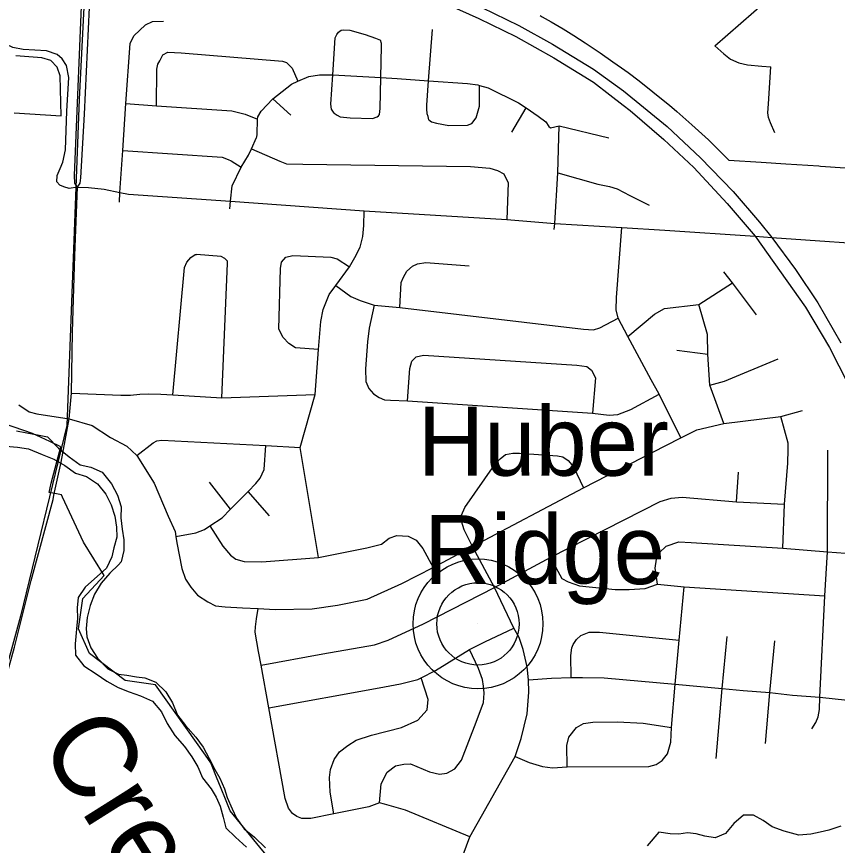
# Model space of a CAD drawing. Extents: x 0 to 34, y 0 to 22.
# Drawn here: x 5.063 to 6.003, y 18.158 to 19.107 of the extents above; entities that cross this region are included whole.
import ezdxf

# ---------------------------------------------------------------- set-up
doc = ezdxf.new("R2010")
doc.units = 0
for name, color, linetype in [('GM_X_City_Street', 7, 'Continuous'), ('GM_X_Corporation', 7, 'Continuous'), ('GM_X_County_Road', 7, 'Continuous'), ('GM_X_Interstate_Route', 7, 'Continuous'), ('GM_X_Major_River', 7, 'Continuous'), ('GM_X_Major_River_Text', 7, 'Continuous'), ('GM_X_Minor_River', 7, 'Continuous'), ('GM_X_Rail_Line', 7, 'Continuous'), ('GM_X_State_Route', 7, 'Continuous'), ('GM_X_Township_Road', 7, 'Continuous'), ('GM_X_Unincorporated', 7, 'Continuous'), ('GM_X_Unincorporated_Location', 7, 'Continuous'), ('GM_X_Unincorporated_Text', 7, 'Continuous')]:
    doc.layers.add(name, color=color, linetype=linetype)

msp = doc.modelspace()

# ---------------------------------------------------------------- linework, layer by layer
at = {"layer": 'GM_X_City_Street'}
for points in [[(5.86241, 19.07357), (5.92215, 19.1255), (5.93857, 19.14031), (5.9445, 19.14416)], [(5.86241, 19.07357), (5.87288, 19.06433), (5.88048, 19.05858), (5.89013, 19.05427), (5.90019, 19.05181), (5.9164, 19.05058), (5.92666, 19.04975)], [(5.93138, 18.97397), (5.92641, 18.98542), (5.92425, 18.99169), (5.92339, 18.99688), (5.92403, 19.00725), (5.92666, 19.04975)]]:
    msp.add_lwpolyline(points, dxfattribs=at)
at = {"layer": 'GM_X_Corporation'}
for points in [[(5.66238, 19.10853), (5.66496, 19.10707), (5.675, 19.10124), (5.68904, 19.09297), (5.70089, 19.0856), (5.7141, 19.07727), (5.73128, 19.06555), (5.74593, 19.0554), (5.75567, 19.04857), (5.76344, 19.04304), (5.765, 19.04185), (5.77435, 19.03465), (5.78348, 19.02753), (5.79972, 19.01466), (5.81061, 19.00587), (5.81902, 18.99853), (5.83621, 18.98326), (5.85542, 18.96589), (5.8787, 18.94287), (5.91583, 18.94045), (5.94405, 18.93858), (5.98175, 18.93608), (5.98364, 18.93595), (6.01191, 18.93408)], [(5.05997, 18.99684), (5.11381, 18.99352), (5.11254, 19.03933), (5.10943, 19.04941), (5.10194, 19.05684), (5.09183, 19.05987), (5.06178, 19.06204)], [(5.3588, 18.13419), (5.33787, 18.15995), (5.30744, 18.19739), (5.3021, 18.21064), (5.29722, 18.22273), (5.29195, 18.2358), (5.2869, 18.24832), (5.28533, 18.2522), (5.27901, 18.26111), (5.22175, 18.34177), (5.18707, 18.34673), (5.14638, 18.37743), (5.13374, 18.40563), (5.13852, 18.44052), (5.16319, 18.46676), (5.13946, 18.50497), (5.11532, 18.55673), (5.11423, 18.55914), (5.11035, 18.55993), (5.09996, 18.56198), (5.10245, 18.57253), (5.11328, 18.61425), (5.1007, 18.62055), (5.08109, 18.62959), (5.03738, 18.64436)]]:
    msp.add_lwpolyline(points, dxfattribs=at)
at = {"layer": 'GM_X_County_Road'}
for points in [[(5.1325, 18.91193), (5.14519, 18.91151), (5.16323, 18.90941), (5.18122, 18.90564), (5.19082, 18.90371), (5.3079, 18.89575), (5.46101, 18.88479), (5.62446, 18.87486), (5.67932, 18.87032), (5.75588, 18.86555), (5.80515, 18.86234)], [(5.80515, 18.86234), (5.90861, 18.8556), (5.92792, 18.85423), (6.07124, 18.84411), (6.08009, 18.84353)]]:
    msp.add_lwpolyline(points, dxfattribs=at)
at = {"layer": 'GM_X_Interstate_Route'}
msp.add_line((5.74217, 19.01763), (5.75777, 19.00562), dxfattribs=at)
for points in [[(4.24891, 19.48616), (4.36443, 19.45657), (4.47706, 19.42735), (4.80123, 19.34181), (4.93621, 19.30635), (5.14378, 19.25182), (5.15288, 19.24943), (5.37233, 19.1927), (5.45831, 19.16923), (5.51314, 19.15256), (5.55876, 19.13413), (5.59561, 19.11769), (5.63794, 19.09707), (5.67679, 19.07577), (5.7235, 19.04681), (5.7579, 19.02224), (5.80795, 18.98123), (5.84611, 18.94527), (5.88361, 18.90666), (5.91388, 18.87157), (5.92792, 18.85423), (5.95512, 18.8174), (5.98056, 18.77923), (6.00688, 18.73361)], [(5.37096, 19.17937), (5.455, 19.15643), (5.509, 19.13981), (5.55545, 19.12134), (5.5923, 19.10489), (5.63463, 19.08427), (5.67806, 19.05993), (5.72346, 19.03204), (5.74217, 19.01763)], [(5.75777, 19.00562), (5.76557, 18.99961), (5.80417, 18.96649), (5.83861, 18.93425), (5.87677, 18.89302), (5.90861, 18.8556), (5.96626, 18.77436), (5.99389, 18.72808), (6.02585, 18.665), (6.03622, 18.64167), (6.04872, 18.61184), (6.05838, 18.58464), (6.07022, 18.54757), (6.07965, 18.51314), (6.08733, 18.4809), (6.09171, 18.4605), (6.09632, 18.43352), (6.10005, 18.40282), (6.104, 18.3754), (6.10575, 18.34755)]]:
    msp.add_lwpolyline(points, dxfattribs=at)
at = {"layer": 'GM_X_Major_River'}
for points in [[(5.06261, 18.63267), (5.07436, 18.63034), (5.08686, 18.628), (5.09823, 18.62567), (5.11068, 18.6127), (5.12315, 18.60277), (5.13562, 18.5936), (5.14775, 18.59089), (5.16061, 18.58513), (5.17155, 18.57179), (5.17831, 18.55885), (5.18242, 18.54555), (5.18236, 18.53302), (5.18381, 18.5201), (5.18565, 18.50757), (5.18558, 18.49542), (5.18249, 18.48252)], [(5.03787, 18.61381), (5.05039, 18.61489), (5.06366, 18.61406), (5.07654, 18.61211), (5.09206, 18.60558), (5.10531, 18.6002), (5.11817, 18.59292), (5.13026, 18.58414), (5.14276, 18.58028), (5.15562, 18.57187), (5.16504, 18.56005), (5.17105, 18.54788), (5.17516, 18.53495), (5.17737, 18.52241), (5.17769, 18.51064), (5.17422, 18.49851), (5.1719, 18.48827), (5.16576, 18.47539), (5.14138, 18.45348), (5.13336, 18.44175), (5.13216, 18.42999), (5.13248, 18.41746), (5.13143, 18.40594)], [(5.18249, 18.48252), (5.17965, 18.47919), (5.16953, 18.46968), (5.15961, 18.45795), (5.15196, 18.44546), (5.14697, 18.43258), (5.14349, 18.41892), (5.14229, 18.40602), (5.14338, 18.39652), (5.14787, 18.38398), (5.1554, 18.37217), (5.16747, 18.35997), (5.17958, 18.35384), (5.18906, 18.35265), (5.20005, 18.3507)], [(5.13143, 18.40594), (5.13092, 18.4012), (5.12969, 18.38862), (5.13038, 18.37571), (5.1398, 18.36351), (5.15379, 18.35434), (5.16627, 18.34592), (5.17913, 18.33865), (5.19162, 18.33366), (5.20487, 18.32904), (5.2185, 18.3229), (5.22868, 18.3107), (5.23544, 18.29738), (5.2441, 18.28367), (5.25503, 18.27109), (5.26332, 18.25929), (5.27047, 18.24786), (5.27572, 18.23493), (5.28552, 18.22236), (5.29154, 18.21284), (5.29604, 18.20256), (5.29939, 18.19002), (5.30237, 18.17786), (5.31369, 18.16717), (5.32615, 18.15572)], [(5.20005, 18.3507), (5.20952, 18.34952), (5.2224, 18.34452), (5.23372, 18.33346), (5.24124, 18.32089), (5.24724, 18.30682), (5.25629, 18.29501), (5.26798, 18.28166), (5.27665, 18.27023), (5.28341, 18.25729), (5.2898, 18.24473), (5.29544, 18.23484), (5.30107, 18.22266), (5.30405, 18.2124), (5.30968, 18.19946), (5.31456, 18.18881), (5.3236, 18.17662), (5.33531, 18.16707), (5.34777, 18.15486)]]:
    msp.add_lwpolyline(points, dxfattribs=at)
at = {"layer": 'GM_X_Minor_River'}
msp.add_lwpolyline([(6.00677, 18.17981), (5.99306, 18.17502), (5.98317, 18.17284), (5.97253, 18.17066), (5.95885, 18.16928), (5.9422, 18.174), (5.92821, 18.17908), (5.91803, 18.18639), (5.9067, 18.19219), (5.89532, 18.19231), (5.88422, 18.18293), (5.875, 18.17125), (5.86281, 18.16644), (5.85106, 18.16845), (5.84122, 18.17083), (5.83136, 18.17207), (5.82148, 18.17064), (5.81124, 18.17112), (5.79835, 18.17277), (5.78492, 18.15734)], dxfattribs=at)
at = {"layer": 'GM_X_Rail_Line'}
msp.add_lwpolyline([(5.013, 20.2642), (5.1449, 19.80142), (5.15727, 19.72918), (5.15969, 19.50896), (5.13444, 19.0127), (5.12013, 18.63864), (5.06738, 18.42023), (5.01943, 18.24707), (4.96758, 18.0163), (4.96155, 17.92727), (4.95651, 17.64256), (4.86303, 17.64736)], dxfattribs=at)
at = {"layer": 'GM_X_State_Route'}
for points in [[(5.1325, 18.91193), (5.12962, 18.91646), (5.12904, 18.92531), (5.13696, 19.11901), (5.13922, 19.15801), (5.13991, 19.17464), (5.14038, 19.18575), (5.14273, 19.2287), (5.14318, 19.23857), (5.14378, 19.25182), (5.1465, 19.30769), (5.14778, 19.34656), (5.14838, 19.35872)], [(5.1325, 18.91193), (5.13544, 18.9162), (5.13638, 18.92253), (5.14047, 18.9954), (5.14611, 19.11753), (5.14843, 19.15766), (5.14913, 19.17429), (5.14959, 19.1854), (5.15162, 19.22642)], [(5.10555, 18.55897), (5.11371, 18.59669), (5.12314, 18.64647), (5.12556, 18.67565), (5.12665, 18.74583), (5.12954, 18.83359), (5.1325, 18.91193)], [(5.0472, 18.33612), (5.06027, 18.38488), (5.0795, 18.46117), (5.1045, 18.55414), (5.10555, 18.55897)]]:
    msp.add_lwpolyline(points, dxfattribs=at)
at = {"layer": 'GM_X_Township_Road'}
for p, q in [((5.53458, 19.03363), (5.53906, 19.09222)), ((5.35621, 19.01294), (5.37675, 18.99444)), ((5.62997, 18.97472), (5.6463, 19.00249)), ((5.68423, 18.98208), (5.74123, 18.96831)), ((5.8192, 18.72521), (5.85449, 18.72052)), ((5.88755, 18.55137), (5.88977, 18.58527)), ((5.30796, 18.54297), (5.28382, 18.57387)), ((5.3525, 18.53533), (5.32789, 18.56317))]:
    msp.add_line(p, q, dxfattribs=at)
for points in [[(5.1325, 18.91193), (5.12293, 18.91011), (5.11676, 18.91231), (5.11234, 18.91408), (5.10882, 18.91783), (5.10926, 18.92511), (5.11279, 18.93327), (5.11587, 18.94054), (5.11896, 18.95444), (5.12028, 18.99899), (5.12249, 19.03736), (5.11984, 19.05104), (5.11499, 19.05898), (5.10926, 19.06382), (5.09692, 19.06779), (5.07046, 19.06956), (5.05855, 19.07176), (5.05062, 19.07573), (5.03739, 19.08368), (5.02008, 19.09142), (5.01777, 19.09728)], [(5.18048, 18.89454), (5.18122, 18.90564), (5.18445, 18.95364), (5.18807, 19.00754), (5.19269, 19.07632), (5.19697, 19.08501), (5.21043, 19.09774), (5.21846, 19.10143), (5.23101, 19.10203)], [(5.42655, 18.99644), (5.42357, 19.00103), (5.42288, 19.00674), (5.42519, 19.04053), (5.42761, 19.08269), (5.42956, 19.08684), (5.43149, 19.08947), (5.43456, 19.09171)], [(5.43456, 19.09171), (5.43687, 19.09215), (5.44444, 19.09158), (5.46224, 19.08678), (5.47396, 19.08245), (5.47964, 19.08009)], [(5.47744, 18.99348), (5.4786, 18.99498), (5.47906, 19.00182), (5.4799, 19.03727), (5.48075, 19.07338), (5.48073, 19.07628), (5.47964, 19.08009)], [(5.22297, 19.00512), (5.22349, 19.04703), (5.2247, 19.05271), (5.22703, 19.05648), (5.23015, 19.06328)], [(5.23015, 19.06328), (5.23589, 19.06624), (5.25146, 19.06566), (5.36724, 19.05613), (5.37178, 19.05455), (5.37855, 19.048), (5.38508, 19.03305)], [(5.33816, 18.97211), (5.33882, 18.98955), (5.3391, 18.99228), (5.34298, 18.99869), (5.35621, 19.01294), (5.37756, 19.02977), (5.38508, 19.03305), (5.3975, 19.03838), (5.40961, 19.04036), (5.42101, 19.04059), (5.42519, 19.04053)], [(5.42519, 19.04053), (5.4799, 19.03727), (5.49886, 19.03613), (5.53458, 19.03363), (5.57935, 19.0305), (5.59111, 19.02883), (5.59307, 19.02829), (5.60285, 19.02563), (5.6376, 19.00845), (5.6463, 19.00249), (5.66021, 18.99295), (5.66888, 18.98675), (5.67261, 18.98138), (5.67449, 18.97983), (5.68423, 18.98208)], [(5.53514, 18.98891), (5.53405, 18.99273), (5.53294, 18.99578), (5.53263, 19.00148), (5.53268, 19.00566), (5.53458, 19.03363)], [(5.58411, 18.98483), (5.58913, 18.99123), (5.59309, 19.00448), (5.59307, 19.02829)], [(5.18807, 19.00754), (5.22297, 19.00512), (5.30916, 18.99914), (5.3247, 18.99552), (5.33882, 18.98955)], [(5.42655, 18.99644), (5.42995, 18.99411), (5.43334, 18.99217), (5.44473, 18.99125), (5.47056, 18.99053), (5.4759, 18.99236), (5.47744, 18.99348)], [(5.53514, 18.98891), (5.53815, 18.98659), (5.54384, 18.985), (5.55787, 18.98253), (5.57914, 18.98262), (5.58411, 18.98483)], [(5.67836, 18.86324), (5.67932, 18.87032), (5.68269, 18.92815), (5.68423, 18.98208)], [(5.30701, 18.88676), (5.3079, 18.89575), (5.30964, 18.91325), (5.32002, 18.93486), (5.3283, 18.94835), (5.33197, 18.9558), (5.33764, 18.96855), (5.33806, 18.9695), (5.33816, 18.97211)], [(5.18445, 18.95364), (5.29826, 18.94609), (5.30506, 18.94333), (5.30846, 18.94177), (5.32002, 18.93486)], [(5.33197, 18.9558), (5.36432, 18.94141), (5.37188, 18.93864), (5.39049, 18.93801), (5.58253, 18.93546), (5.60487, 18.93353), (5.61373, 18.93084), (5.62105, 18.92699), (5.62568, 18.91659), (5.62446, 18.87486)], [(5.68269, 18.92815), (5.72842, 18.91528), (5.74207, 18.91244), (5.75078, 18.91004), (5.76512, 18.90225), (5.78741, 18.89131)], [(5.40854, 18.48746), (5.38769, 18.61351), (5.40475, 18.67419), (5.40861, 18.72596), (5.41118, 18.75779), (5.41407, 18.77162), (5.42082, 18.78866), (5.42854, 18.79895), (5.44429, 18.82048), (5.45008, 18.8311), (5.45651, 18.84299), (5.4594, 18.85521), (5.46037, 18.86775), (5.46101, 18.88479)], [(5.78977, 18.69096), (5.76281, 18.74055), (5.75183, 18.76154), (5.74971, 18.77117), (5.74991, 18.78523), (5.75588, 18.86555)], [(5.24168, 18.67392), (5.25529, 18.81974), (5.25765, 18.82579), (5.26227, 18.83105), (5.26725, 18.83478), (5.26877, 18.83476)], [(5.29792, 18.67024), (5.30437, 18.8244), (5.3044, 18.82706), (5.3014, 18.83014), (5.29725, 18.83248), (5.26877, 18.83476)], [(5.40861, 18.72596), (5.38224, 18.72789), (5.37453, 18.73271), (5.36809, 18.73946), (5.36327, 18.74911), (5.3652, 18.81856), (5.36617, 18.82595), (5.37131, 18.83142), (5.37903, 18.83367), (5.42276, 18.83142), (5.42983, 18.82949), (5.44429, 18.82048)], [(5.50184, 18.77387), (5.50345, 18.80248), (5.50603, 18.80859), (5.50988, 18.81566), (5.51632, 18.82113), (5.5221, 18.82402), (5.53143, 18.82531), (5.58126, 18.82177)], [(5.91034, 18.76558), (5.883, 18.80218), (5.87298, 18.81489)], [(5.76281, 18.74055), (5.79363, 18.76635), (5.8048, 18.7729), (5.84409, 18.77753), (5.883, 18.80218)], [(5.42854, 18.79895), (5.44558, 18.78641), (5.45651, 18.7819), (5.47227, 18.77676), (5.50184, 18.77387), (5.71233, 18.74904), (5.72372, 18.74852), (5.73097, 18.7507), (5.75183, 18.76154)], [(5.47227, 18.77676), (5.4668, 18.7504), (5.46455, 18.73464), (5.4623, 18.70378), (5.46294, 18.68899), (5.46616, 18.68127), (5.47162, 18.67516), (5.47805, 18.67066), (5.48416, 18.66808), (5.49091, 18.66777), (5.51052, 18.66712), (5.72249, 18.65269), (5.74165, 18.65049), (5.7516, 18.65122), (5.76634, 18.65712), (5.79876, 18.67444)], [(5.87281, 18.64091), (5.85697, 18.68512), (5.85449, 18.72052), (5.8541, 18.74286), (5.84409, 18.77753)], [(5.51052, 18.66712), (5.5131, 18.7041), (5.51567, 18.71246), (5.52058, 18.71754), (5.52869, 18.71939), (5.70444, 18.70796), (5.71586, 18.70649), (5.72139, 18.70207), (5.72581, 18.69323), (5.72249, 18.65269)], [(5.85697, 18.68512), (5.87355, 18.68954), (5.93508, 18.71496)], [(5.82381, 18.62469), (5.79876, 18.67444), (5.78977, 18.69096)], [(5.12556, 18.67565), (5.18236, 18.67367), (5.19333, 18.67367), (5.20386, 18.67477), (5.214, 18.67513), (5.22784, 18.67452)], [(5.22784, 18.67452), (5.24168, 18.67392), (5.29792, 18.67024), (5.40475, 18.67419)], [(5.06524, 18.66249), (5.07709, 18.65437), (5.08586, 18.65196), (5.12314, 18.64647)], [(5.80664, 18.61585), (5.82381, 18.62469), (5.84186, 18.6339), (5.87281, 18.64091), (5.93803, 18.64901), (5.96314, 18.65603)], [(5.94064, 18.49812), (5.94245, 18.54843), (5.94614, 18.59559), (5.9465, 18.61143), (5.9465, 18.61843), (5.93803, 18.64901)], [(5.12314, 18.64647), (5.14946, 18.63858), (5.17045, 18.62517), (5.18895, 18.61504), (5.20068, 18.60446), (5.22034, 18.57282), (5.23622, 18.53498), (5.24437, 18.51739), (5.24534, 18.51144), (5.24649, 18.50445), (5.2522, 18.47473), (5.25623, 18.46251), (5.26221, 18.45369), (5.27007, 18.44447), (5.28175, 18.43671), (5.29044, 18.43203), (5.30183, 18.43113), (5.32157, 18.42972), (5.33944, 18.42893), (5.35879, 18.42808), (5.40136, 18.42865), (5.43029, 18.43283), (5.4642, 18.43959), (5.50418, 18.45782), (5.53991, 18.4761), (5.58519, 18.5002), (5.71218, 18.56722), (5.80664, 18.61585)], [(5.20068, 18.60446), (5.21939, 18.61881), (5.22359, 18.62103), (5.22931, 18.6221), (5.34823, 18.61565), (5.38769, 18.61351)], [(5.24534, 18.51144), (5.26791, 18.51594), (5.27783, 18.51961), (5.28415, 18.52378), (5.29814, 18.53302), (5.30796, 18.54297), (5.32789, 18.56317), (5.337, 18.5724), (5.34164, 18.57842), (5.34631, 18.58824), (5.34823, 18.61565)], [(5.58519, 18.5002), (5.57564, 18.51931), (5.57232, 18.52928), (5.57235, 18.53609), (5.57622, 18.54493), (5.61048, 18.59393), (5.61675, 18.60056), (5.62283, 18.60535), (5.63131, 18.6072), (5.63886, 18.6072), (5.68251, 18.60388), (5.68841, 18.60277), (5.69467, 18.59872), (5.70057, 18.59154), (5.71218, 18.56722)], [(5.97387, 18.29107), (5.97844, 18.29849), (5.98114, 18.30493), (5.98239, 18.31344), (5.9828, 18.32736), (5.98841, 18.4437), (5.99174, 18.49396), (5.99222, 18.61043)], [(5.34277, 18.36422), (5.41365, 18.37718), (5.47268, 18.38742), (5.48832, 18.39291), (5.52869, 18.4117), (5.61012, 18.45325), (5.67473, 18.48773), (5.79987, 18.55175), (5.81239, 18.55543), (5.82529, 18.55654), (5.88755, 18.55137), (5.94245, 18.54843)], [(5.28415, 18.52378), (5.29887, 18.50033), (5.30788, 18.49032), (5.3139, 18.48568), (5.32336, 18.4829), (5.3435, 18.48263), (5.40854, 18.48746), (5.46378, 18.49851), (5.48093, 18.50284), (5.48964, 18.50975), (5.49836, 18.51266), (5.51125, 18.51183), (5.52039, 18.50726), (5.52828, 18.49771), (5.53991, 18.4761)], [(5.60771, 17.95043), (5.6051, 17.95859), (5.59941, 17.97641), (5.5742, 18.05748), (5.57087, 18.07413), (5.56969, 18.08979), (5.57047, 18.11213), (5.57224, 18.13543), (5.57439, 18.14699), (5.58203, 18.16737), (5.63402, 18.25964), (5.64087, 18.28), (5.64752, 18.30845), (5.64939, 18.33318), (5.64897, 18.3473), (5.64773, 18.36226), (5.64295, 18.38221), (5.63859, 18.39571), (5.63236, 18.40672), (5.61012, 18.45325), (5.58519, 18.5002)], [(5.79688, 18.45699), (5.79439, 18.47527), (5.79563, 18.48566), (5.79896, 18.49272), (5.80685, 18.50061), (5.8214, 18.5056), (5.83552, 18.50477), (5.94064, 18.49812), (5.99174, 18.49396), (6.03287, 18.49106)], [(5.67473, 18.48773), (5.68055, 18.4761), (5.6872, 18.46364), (5.69467, 18.45948), (5.70755, 18.45491), (5.74827, 18.45075), (5.76447, 18.45075), (5.78275, 18.452), (5.79688, 18.45699), (5.82763, 18.45408), (5.98841, 18.4437)], [(5.63402, 18.25964), (5.6498, 18.25257), (5.66518, 18.24801), (5.67681, 18.24655), (5.69343, 18.24759), (5.78691, 18.24801), (5.79522, 18.2505), (5.80228, 18.25507), (5.80851, 18.26255), (5.81226, 18.27585), (5.81308, 18.29288), (5.81724, 18.34232), (5.82181, 18.393), (5.82763, 18.45408)], [(5.58203, 18.16737), (5.50841, 18.19792), (5.48413, 18.20478), (5.47831, 18.20643), (5.46622, 18.20206), (5.4567, 18.19991), (5.42615, 18.19377), (5.39993, 18.1885), (5.38968, 18.18864), (5.38362, 18.19062), (5.37873, 18.1941), (5.37424, 18.20024), (5.37057, 18.21131), (5.35166, 18.3153), (5.34277, 18.36422), (5.33996, 18.37969), (5.33606, 18.40216), (5.33651, 18.40824), (5.33776, 18.41734), (5.33944, 18.42893)], [(5.35166, 18.3153), (5.47816, 18.33832), (5.50253, 18.34294), (5.52235, 18.34762), (5.52614, 18.34956), (5.54261, 18.35799), (5.58167, 18.38199), (5.59932, 18.39072), (5.63236, 18.40672)], [(5.698, 18.35021), (5.69758, 18.37535), (5.69883, 18.38386), (5.70028, 18.38802), (5.70423, 18.39342), (5.70921, 18.39799), (5.71877, 18.40214), (5.7304, 18.40214), (5.82181, 18.393)], [(5.86398, 18.25715), (5.87104, 18.33754), (5.87665, 18.39716)], [(5.92069, 18.2746), (5.92568, 18.33297), (5.9315, 18.39217)], [(5.47831, 18.20643), (5.48025, 18.22829), (5.48738, 18.24141), (5.49693, 18.24869), (5.50649, 18.2508), (5.51393, 18.25096), (5.5358, 18.24205), (5.54729, 18.2393), (5.55554, 18.24042), (5.56478, 18.24545), (5.57232, 18.25548), (5.58915, 18.29869), (5.59745, 18.32155), (5.59849, 18.33193), (5.59766, 18.34024), (5.59662, 18.34772), (5.59205, 18.36039), (5.58167, 18.38199)], [(5.42615, 18.19377), (5.42197, 18.21861), (5.42103, 18.23534), (5.42228, 18.24483), (5.42661, 18.25617), (5.43279, 18.26483), (5.44238, 18.2723), (5.45157, 18.27826), (5.46913, 18.2841), (5.50381, 18.29277), (5.52254, 18.30125), (5.53324, 18.31287), (5.53422, 18.32466), (5.52614, 18.34956)], [(5.64897, 18.3473), (5.67556, 18.34938), (5.698, 18.35021), (5.71088, 18.35021), (5.73581, 18.34979), (5.81724, 18.34232), (5.87104, 18.33754), (5.89514, 18.33525), (5.92568, 18.33297), (5.95144, 18.32985), (5.9828, 18.32736), (6.01459, 18.32404), (6.02394, 18.32362), (6.03266, 18.32508), (6.03993, 18.32757), (6.04762, 18.33235)], [(5.69343, 18.24759), (5.69301, 18.2721), (5.69551, 18.28166), (5.70423, 18.29288), (5.71212, 18.29744), (5.72293, 18.29869), (5.75118, 18.29911), (5.78068, 18.29786), (5.81308, 18.29288)]]:
    msp.add_lwpolyline(points, dxfattribs=at)
at = {"layer": 'GM_X_Unincorporated'}
for radius in [0.0744, 0.04716]:
    msp.add_circle((5.5913, 18.41147), radius, dxfattribs=at)
at = {"layer": 'GM_X_Unincorporated_Location'}
msp.add_line((5.5913, 18.41147), (5.5913, 18.41147), dxfattribs=at)

# ---------------------------------------------------------------- texts
at = {"layer": 'GM_X_Major_River_Text'}
msp.add_text('Creek', height=0.094698, rotation=302.20621, dxfattribs=at).set_placement((5.08685, 18.27502))
at = {"layer": 'GM_X_Unincorporated_Text'}
for s, p in [('Huber', (5.52214, 18.58123)), ('Ridge', (5.52964, 18.45706))]:
    msp.add_text(s, height=0.078977, rotation=0.00001, dxfattribs=at).set_placement(p)

doc.saveas('drawing.dxf')
